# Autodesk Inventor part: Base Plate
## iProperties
Created: 2006-10
Part Number: Base Plate
Document SubType Name: Modeling
Designer: Lab User
Author: Lab User
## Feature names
1. Extrusion1
2. Hole1
3. Hole2
4. Hole3
